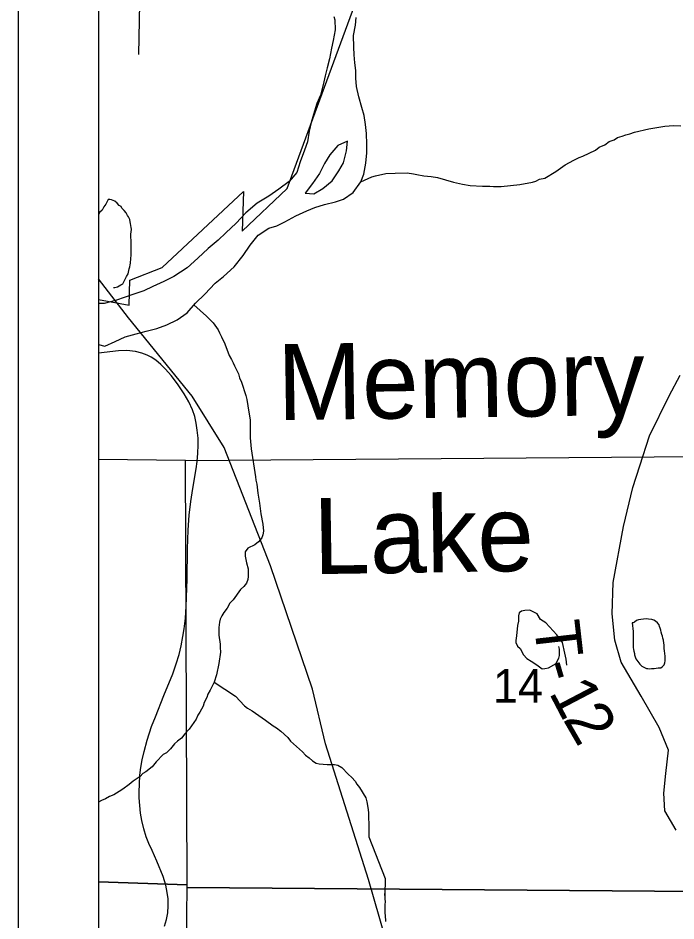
# Model space of a CAD drawing. Extents: x -14196 to 143, y -6096 to 28.
# Drawn here: x 58.003 to 58.822, y 20.825 to 21.949 of the extents above; entities that cross this region are included whole.
import ezdxf

# ---------------------------------------------------------------- set-up
doc = ezdxf.new("R2010")
doc.units = 0
for name, color, linetype in [('GM_X_City_Street', 7, 'Continuous'), ('GM_X_Corporation', 7, 'Continuous'), ('GM_X_County_Road', 7, 'Continuous'), ('GM_X_Major_River', 7, 'Continuous'), ('GM_X_Minor_Lake', 7, 'Continuous'), ('GM_X_Minor_Lake_Text', 7, 'Continuous'), ('GM_X_Minor_River', 7, 'Continuous'), ('GM_X_Rail_Line', 7, 'Continuous'), ('GM_X_Section_Text', 7, 'Continuous'), ('GM_X_Township_Road', 7, 'Continuous'), ('GM_X_Township_Road_Text', 7, 'Continuous'), ('SH_Data', 7, 'Continuous')]:
    doc.layers.add(name, color=color, linetype=linetype)

msp = doc.modelspace()

# ---------------------------------------------------------------- linework, layer by layer
at = {"layer": 'GM_X_City_Street'}
msp.add_lwpolyline([(58.1532, 21.903), (58.1543, 21.9668), (58.1586, 22.1016), (58.1596, 22.1811), (58.1618, 22.2231), (58.1627, 22.2518), (58.1642, 22.293)], dxfattribs=at)
at = {"layer": 'GM_X_Corporation'}
for points in [[(64.9028, 18.7286), (64.9028, 23.6985), (58.1028, 23.6985), (58.1028, 18.8711)], [(62.1999, 18.7816), (62.2235, 19.866), (62.2323, 20.4208), (62.2487, 21.1358), (62.2751, 22.2884), (62.2815, 22.5484), (62.2824, 22.5866), (62.306, 23.4402), (61.9207, 23.4521), (60.7524, 23.485), (60.7179, 23.4857), (60.6994, 23.486), (60.6731, 23.4865), (60.4232, 23.4912), (60.4233, 23.5426), (60.4242, 23.5839), (60.4246, 23.6029), (60.4257, 23.6513), (60.4267, 23.6985), (58.1028, 23.6985), (58.1028, 18.8711)], [(58.1028, 23.2195), (58.1028, 21.5984), (58.1411, 21.5913), (58.1421, 21.6226), (58.1823, 21.6381), (58.2833, 21.7327), (58.2817, 21.6832), (58.3377, 21.7363), (58.4221, 21.9651)]]:
    msp.add_lwpolyline(points, dxfattribs=at)
for points in [[(58.2114, 21.3981), (59.2186, 21.4059), (59.2185, 20.859), (58.2134, 20.8668), (58.2133, 20.8703)], [(58.1028, 21.3991), (58.1028, 20.874), (58.2133, 20.8703), (58.2114, 21.3981)], [(58.1028, 20.874), (58.1028, 19.8822), (58.2013, 19.8806), (58.2134, 20.8668), (58.2133, 20.8703)], [(59.2185, 20.859), (59.2056, 19.8463), (58.2013, 19.8806), (58.2134, 20.8668)]]:
    msp.add_lwpolyline(points, close=True, dxfattribs=at)
at = {"layer": 'GM_X_County_Road'}
msp.add_lwpolyline([(58.1851, 20.8185), (58.1878, 20.8268), (58.1893, 20.8351), (58.1898, 20.8439), (58.1897, 20.8526), (58.1886, 20.8606), (58.1869, 20.8697), (58.1834, 20.8805), (58.1755, 20.8994), (58.1696, 20.9127), (58.1658, 20.9216), (58.1624, 20.93), (58.1593, 20.9396), (58.157, 20.9501), (58.1553, 20.9593), (58.1544, 20.9687), (58.1538, 20.9783), (58.1536, 20.9859), (58.1539, 20.9952), (58.1546, 21.0066), (58.1558, 21.0161), (58.1573, 21.0258), (58.1597, 21.0362), (58.1636, 21.0501), (58.1691, 21.0672), (58.1738, 21.0793), (58.1845, 21.1057), (58.1955, 21.1325), (58.1998, 21.1451), (58.2032, 21.1566), (58.2057, 21.1674), (58.208, 21.179), (58.2097, 21.1888), (58.2111, 21.2019), (58.2122, 21.2164), (58.2133, 21.2505), (58.2136, 21.2883), (58.2146, 21.3114), (58.216, 21.3299), (58.218, 21.347), (58.2203, 21.3631), (58.2246, 21.3877), (58.2257, 21.397), (58.2268, 21.4073), (58.2271, 21.4171), (58.227, 21.4258), (58.226, 21.4356), (58.2247, 21.4447), (58.2229, 21.4528), (58.2201, 21.4612), (58.2154, 21.4709), (58.2096, 21.4812), (58.2012, 21.4936), (58.1933, 21.5039), (58.1864, 21.5118), (58.1806, 21.5176), (58.1743, 21.5228), (58.1685, 21.5266), (58.1634, 21.5293), (58.1569, 21.5318), (58.1489, 21.5337), (58.1384, 21.5349), (58.1277, 21.5345), (58.1028, 21.5317)], dxfattribs=at)
at = {"layer": 'GM_X_Major_River'}
for p, q in [((58.3909, 21.7783), (58.3843, 21.7676)), ((58.4022, 21.7583), (58.4078, 21.7682))]:
    msp.add_line(p, q, dxfattribs=at)
for points in [[(58.3959, 21.9506), (58.3971, 21.9465)], [(58.3971, 21.9465), (58.3977, 21.934), (58.3952, 21.9206), (58.393, 21.9111), (58.3906, 21.8978), (58.3877, 21.8864), (58.3851, 21.8765), (58.3826, 21.8655), (58.3794, 21.8525), (58.3749, 21.8422), (58.372, 21.8327), (58.3677, 21.8186), (58.3651, 21.8079), (58.363, 21.7946), (58.3594, 21.784), (58.3539, 21.7695), (58.3499, 21.7565), (58.3405, 21.745), (58.3274, 21.7357), (58.315, 21.7269), (58.3006, 21.7183), (58.2864, 21.706), (58.2744, 21.6933), (58.2616, 21.6814), (58.2519, 21.6722), (58.2395, 21.6618), (58.2268, 21.6498), (58.2133, 21.6379), (58.1967, 21.6271), (58.1843, 21.6208), (58.1707, 21.6146), (58.1594, 21.6091), (58.148, 21.6056), (58.1363, 21.6013), (58.1242, 21.5973), (58.1102, 21.5933), (58.1028, 21.5935)], [(58.4365, 21.8047), (58.4352, 21.816), (58.4336, 21.8274), (58.4308, 21.8372), (58.4272, 21.8505), (58.424, 21.8633), (58.4235, 21.8739), (58.4234, 21.8834), (58.4221, 21.8929), (58.4212, 21.9028), (58.4207, 21.9122), (58.4205, 21.927), (58.4227, 21.9396), (58.4237, 21.9491)], [(58.1028, 21.5423), (58.1109, 21.5402), (58.1237, 21.5461), (58.1362, 21.5519), (58.1498, 21.5555), (58.1623, 21.5591), (58.1755, 21.5623), (58.188, 21.567), (58.2008, 21.5732), (58.2132, 21.5817), (58.2237, 21.594), (58.2353, 21.6048), (58.2484, 21.6186), (58.2586, 21.6271), (58.2717, 21.639), (58.2829, 21.6532), (58.2918, 21.6658), (58.3019, 21.6785), (58.3151, 21.687), (58.3249, 21.6902), (58.3351, 21.6952), (58.3487, 21.7026), (58.3622, 21.7085), (58.3721, 21.7128), (58.3845, 21.7167), (58.3978, 21.7199), (58.408, 21.7231), (58.42, 21.7316), (58.4297, 21.7446), (58.4334, 21.7541), (58.4359, 21.7678), (58.4372, 21.7808), (58.4371, 21.7918), (58.4365, 21.8047)], [(58.4078, 21.7682), (58.4117, 21.7835), (58.4131, 21.7953), (58.401, 21.7898), (58.3909, 21.7783)], [(58.3843, 21.7676), (58.378, 21.755), (58.3694, 21.7427), (58.3601, 21.7308), (58.3711, 21.7298), (58.3824, 21.7364), (58.394, 21.7461), (58.4022, 21.7583)]]:
    msp.add_lwpolyline(points, dxfattribs=at)
at = {"layer": 'GM_X_Minor_Lake'}
for points in [[(58.1166, 21.7226), (58.115, 21.7226), (58.1143, 21.7211), (58.112, 21.7169), (58.1097, 21.7135), (58.1075, 21.7097), (58.1044, 21.7066), (58.1028, 21.7046)], [(58.1166, 21.7226), (58.115, 21.7226), (58.1143, 21.7211), (58.112, 21.7169), (58.1097, 21.7135), (58.1075, 21.7097), (58.1044, 21.7066), (58.1028, 21.7046)], [(58.1215, 21.6133), (58.1235, 21.6133), (58.1265, 21.6141), (58.1288, 21.6152), (58.1307, 21.6167), (58.1333, 21.6179), (58.1379, 21.627), (58.1401, 21.6304), (58.1413, 21.6365), (58.142, 21.6392), (58.1424, 21.6415), (58.1427, 21.6437), (58.1431, 21.6494), (58.1435, 21.6536), (58.1438, 21.6578), (58.1438, 21.6612), (58.1438, 21.6661), (58.1438, 21.6699), (58.1438, 21.6726), (58.1434, 21.6749), (58.1434, 21.6772), (58.1434, 21.6802), (58.1437, 21.6821), (58.1441, 21.6859), (58.1437, 21.6878), (58.1433, 21.6905), (58.1426, 21.6931), (58.1425, 21.695), (58.1418, 21.698), (58.1402, 21.7011), (58.1391, 21.703), (58.1376, 21.706), (58.1349, 21.709), (58.1322, 21.7121), (58.1311, 21.714), (58.1288, 21.7155), (58.1261, 21.7181), (58.1234, 21.7208), (58.1192, 21.7223), (58.1169, 21.7226), (58.1166, 21.7226)], [(58.6859, 21.1436), (58.685, 21.1508), (58.6836, 21.1584), (58.6807, 21.1716), (58.6735, 21.181), (58.6598, 21.196), (58.653, 21.2001), (58.6492, 21.2072), (58.6458, 21.2091), (58.6399, 21.2117), (58.6338, 21.2116), (58.6294, 21.2107), (58.6267, 21.2084), (58.6257, 21.2046), (58.6257, 21.1981), (58.6245, 21.1928), (58.6233, 21.1799), (58.6225, 21.1742), (58.6227, 21.1715), (58.6246, 21.167), (58.6277, 21.164), (58.6319, 21.1564), (58.6363, 21.1516), (58.6414, 21.1482), (58.6487, 21.1438), (58.6551, 21.1389), (58.6588, 21.1394), (58.6632, 21.1402), (58.6726, 21.1457), (58.6744, 21.1491), (58.6759, 21.1522), (58.6769, 21.1556), (58.6768, 21.1632), (58.6761, 21.1666)], [(58.8085, 21.1524), (58.8085, 21.1543), (58.8081, 21.1585), (58.8077, 21.1608), (58.8073, 21.1646), (58.8073, 21.1688), (58.8069, 21.171), (58.8062, 21.1745), (58.8054, 21.1771), (58.805, 21.1794), (58.8042, 21.1817), (58.8035, 21.1843), (58.8031, 21.187), (58.8023, 21.1896), (58.8015, 21.1915), (58.8008, 21.1934), (58.7988, 21.1961), (58.7965, 21.1983), (58.7943, 21.1995), (58.792, 21.2002), (58.7878, 21.2006), (58.7847, 21.201), (58.7813, 21.2006), (58.7779, 21.2002), (58.7752, 21.1998), (58.7729, 21.199), (58.7703, 21.1971), (58.7684, 21.1963), (58.7672, 21.196)], [(58.7672, 21.196), (58.7684, 21.1853), (58.7685, 21.1774), (58.7685, 21.1713), (58.7685, 21.1686), (58.7685, 21.1656), (58.7689, 21.1629), (58.7693, 21.1607), (58.7701, 21.158), (58.7704, 21.1561), (58.7712, 21.1538), (58.772, 21.1515), (58.7743, 21.1478), (58.777, 21.1447), (58.7793, 21.1421), (58.7812, 21.1413), (58.785, 21.1394), (58.7869, 21.1391), (58.7892, 21.1387), (58.7914, 21.1391), (58.7945, 21.1391), (58.7998, 21.1399), (58.8029, 21.1403), (58.8048, 21.1414), (58.807, 21.1437), (58.8078, 21.1464), (58.8085, 21.149), (58.8085, 21.1524), (58.8085, 21.1543), (58.8081, 21.1585), (58.8077, 21.1608), (58.8073, 21.1646), (58.8073, 21.1688), (58.8069, 21.171), (58.8062, 21.1745), (58.8054, 21.1771), (58.805, 21.1794), (58.8042, 21.1817), (58.8035, 21.1843), (58.8031, 21.187), (58.8023, 21.1896), (58.8015, 21.1915), (58.8008, 21.1934), (58.7988, 21.1961), (58.7965, 21.1983), (58.7943, 21.1995), (58.792, 21.2002), (58.7878, 21.2006), (58.7847, 21.201), (58.7813, 21.2006), (58.7779, 21.2002), (58.7752, 21.1998), (58.7729, 21.199), (58.7703, 21.1971), (58.7684, 21.1963), (58.7672, 21.196)], [(58.7672, 21.196), (58.7684, 21.1853), (58.7685, 21.1774), (58.7685, 21.1713), (58.7685, 21.1686), (58.7685, 21.1656), (58.7689, 21.1629), (58.7693, 21.1607), (58.7701, 21.158), (58.7704, 21.1561), (58.7712, 21.1538), (58.772, 21.1515), (58.7743, 21.1478), (58.777, 21.1447), (58.7793, 21.1421), (58.7812, 21.1413), (58.785, 21.1394), (58.7869, 21.1391), (58.7892, 21.1387), (58.7914, 21.1391), (58.7945, 21.1391), (58.7998, 21.1399), (58.8029, 21.1403), (58.8048, 21.1414), (58.807, 21.1437), (58.8078, 21.1464), (58.8085, 21.149), (58.8085, 21.1524)]]:
    msp.add_lwpolyline(points, dxfattribs=at)
at = {"layer": 'GM_X_Minor_River'}
for points in [[(58.4297, 21.7446), (58.4433, 21.7509), (58.4479, 21.7524), (58.4608, 21.7552), (58.4722, 21.7557), (58.4871, 21.7559), (58.4951, 21.7548), (58.4993, 21.7537), (58.508, 21.7523), (58.5172, 21.7516), (58.5248, 21.7501), (58.5447, 21.7442), (58.5561, 21.7417), (58.5656, 21.7403), (58.5809, 21.7393), (58.5851, 21.7393), (58.59, 21.7394), (58.5946, 21.739), (58.6041, 21.7391), (58.6273, 21.7416), (58.6432, 21.7444), (58.6474, 21.7456), (58.652, 21.748), (58.6584, 21.7495), (58.6724, 21.7576), (58.6841, 21.7661), (58.6947, 21.7719), (58.7012, 21.775), (58.7057, 21.7766), (58.7216, 21.7843), (58.7262, 21.7878), (58.7334, 21.7909), (58.7386, 21.7948), (58.7451, 21.7971), (58.7489, 21.7998), (58.7549, 21.8014), (58.7595, 21.8033), (58.7644, 21.8045), (58.7701, 21.8065), (58.788, 21.8108), (58.8081, 21.8141), (58.8188, 21.8149), (58.8279, 21.8143)], [(58.2216, 21.5916), (58.2373, 21.5775), (58.2458, 21.5692), (58.2519, 21.5605), (58.2535, 21.5567), (58.2562, 21.5518), (58.2601, 21.5431), (58.2656, 21.5287), (58.2687, 21.5238), (58.2706, 21.5197), (58.2722, 21.5159), (58.2773, 21.5057), (58.2784, 21.5011), (58.2808, 21.4954), (58.2863, 21.4788), (58.2875, 21.4738), (58.2887, 21.4659), (58.2903, 21.4583), (58.2916, 21.4488), (58.2916, 21.4446), (58.2918, 21.4264), (58.2931, 21.4127), (58.2984, 21.3778), (58.2988, 21.3736), (58.3, 21.3687), (58.3013, 21.3573), (58.3033, 21.3448), (58.3049, 21.3315), (58.3077, 21.319), (58.3082, 21.3103), (58.3075, 21.3057), (58.3064, 21.3019), (58.3023, 21.2969), (58.2977, 21.2931), (58.289, 21.2888), (58.2856, 21.2846), (58.2857, 21.2789), (58.2873, 21.2709), (58.2893, 21.2633), (58.2894, 21.2538), (58.2887, 21.25), (58.2872, 21.2455), (58.2838, 21.2412), (58.2797, 21.2374), (58.2707, 21.2248), (58.2665, 21.2206), (58.2631, 21.2144), (58.259, 21.2091), (58.2564, 21.2049), (58.2545, 21.2007), (58.2534, 21.1969), (58.2527, 21.1904), (58.2528, 21.1809), (58.2545, 21.1695), (58.2545, 21.1653), (58.255, 21.1596), (58.2528, 21.1456), (58.2499, 21.1315), (58.247, 21.1223), (58.2421, 21.1124), (58.2391, 21.1074), (58.2377, 21.1032), (58.2347, 21.0971), (58.2332, 21.0925), (58.2291, 21.0849), (58.2268, 21.0811), (58.2246, 21.0761), (58.216, 21.0639), (58.2103, 21.0581), (58.2062, 21.0528), (58.2013, 21.0489), (58.1975, 21.0455), (58.1926, 21.0393), (58.1877, 21.0343), (58.1836, 21.0324), (58.1749, 21.0232), (58.1697, 21.0171), (58.1621, 21.0109), (58.1583, 21.0086), (58.1549, 21.0048), (58.1462, 20.999), (58.1413, 20.9948), (58.1334, 20.989), (58.1285, 20.9863), (58.1221, 20.982), (58.1167, 20.9801), (58.1118, 20.977), (58.1069, 20.975), (58.1028, 20.9728)], [(58.247, 21.1224), (58.2734, 21.1047), (58.2846, 21.093), (58.2884, 21.09), (58.2942, 21.0867), (58.311, 21.0751), (58.3202, 21.0679), (58.3245, 21.0653), (58.3298, 21.0612), (58.3387, 21.0533), (58.3421, 21.0488), (58.3571, 21.0356), (58.3606, 21.0315), (58.3652, 21.0281), (58.3694, 21.0243), (58.374, 21.0213), (58.3778, 21.0206), (58.3877, 21.0199), (58.3969, 21.02), (58.4011, 21.0189), (58.406, 21.0159), (58.4137, 21.0077), (58.4184, 21.0035), (58.4226, 20.999), (58.4245, 20.9952), (58.428, 20.9911), (58.4357, 20.9782), (58.4369, 20.9733), (58.4386, 20.9638), (58.439, 20.9593), (58.439, 20.9543), (58.4395, 20.9452), (58.4397, 20.93), (58.46, 20.8778)], [(58.46, 20.8778), (58.4593, 20.8569), (58.4593, 20.8595), (58.4593, 20.8569), (58.4594, 20.8527), (58.4598, 20.8489), (58.4594, 20.8458), (58.4595, 20.8424), (58.4595, 20.8386), (58.4596, 20.8363), (58.4596, 20.8344), (58.46, 20.8325), (58.46, 20.8299), (58.4601, 20.8272), (58.4601, 20.8246)]]:
    msp.add_lwpolyline(points, dxfattribs=at)
at = {"layer": 'GM_X_Rail_Line'}
msp.add_lwpolyline([(58.475, 20.7516), (58.439, 20.8767), (58.3857, 21.0455), (58.3694, 21.1137), (58.3169, 21.2669), (58.2593, 21.4142), (58.2195, 21.4782), (58.1403, 21.5756), (58.1028, 21.624)], dxfattribs=at)
at = {"layer": 'GM_X_Township_Road'}
msp.add_lwpolyline([(58.8221, 20.9383), (58.8081, 20.9621), (58.8067, 20.9841), (58.8094, 21.0088), (58.8125, 21.0377), (58.8011, 21.0657), (58.7785, 21.1049), (58.7536, 21.1471), (58.7456, 21.1747), (58.7425, 21.2073), (58.7435, 21.2461), (58.7564, 21.3158), (58.7683, 21.3646), (58.7767, 21.3913), (58.7888, 21.4286), (58.8133, 21.4784), (58.827, 21.5044)], dxfattribs=at)
at = {"layer": 'SH_Data'}
for p, q in [((58.0028, 23.7985), (58.0028, 16.7985)), ((58.1028, 23.6985), (58.1028, 16.8985))]:
    msp.add_line(p, q, dxfattribs=at)

# ---------------------------------------------------------------- texts
at = {"layer": 'GM_X_Minor_Lake_Text'}
for s, rotation, p in [('Memory', 0.8649, (58.3262, 21.4481)), ('Lake', 0.8655, (58.371, 21.2566))]:
    msp.add_text(s, height=0.0947, rotation=rotation, dxfattribs=at).set_placement(p)
at = {"layer": 'GM_X_Section_Text'}
msp.add_text('14', height=0.04186, rotation=0, dxfattribs=at).set_placement((58.594, 21.0966))
at = {"layer": 'GM_X_Township_Road_Text'}
for s, rotation, p in [('T', 276.5281, (58.6449, 21.1959)), ('-', 286.3559, (58.6519, 21.1433)), ('1', 297.6305, (58.663, 21.1096)), ('2', 300.0868, (58.6805, 21.0763))]:
    msp.add_text(s, height=0.0568, rotation=rotation, dxfattribs=at).set_placement(p)

doc.saveas('drawing.dxf')
